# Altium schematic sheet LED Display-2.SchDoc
size A4
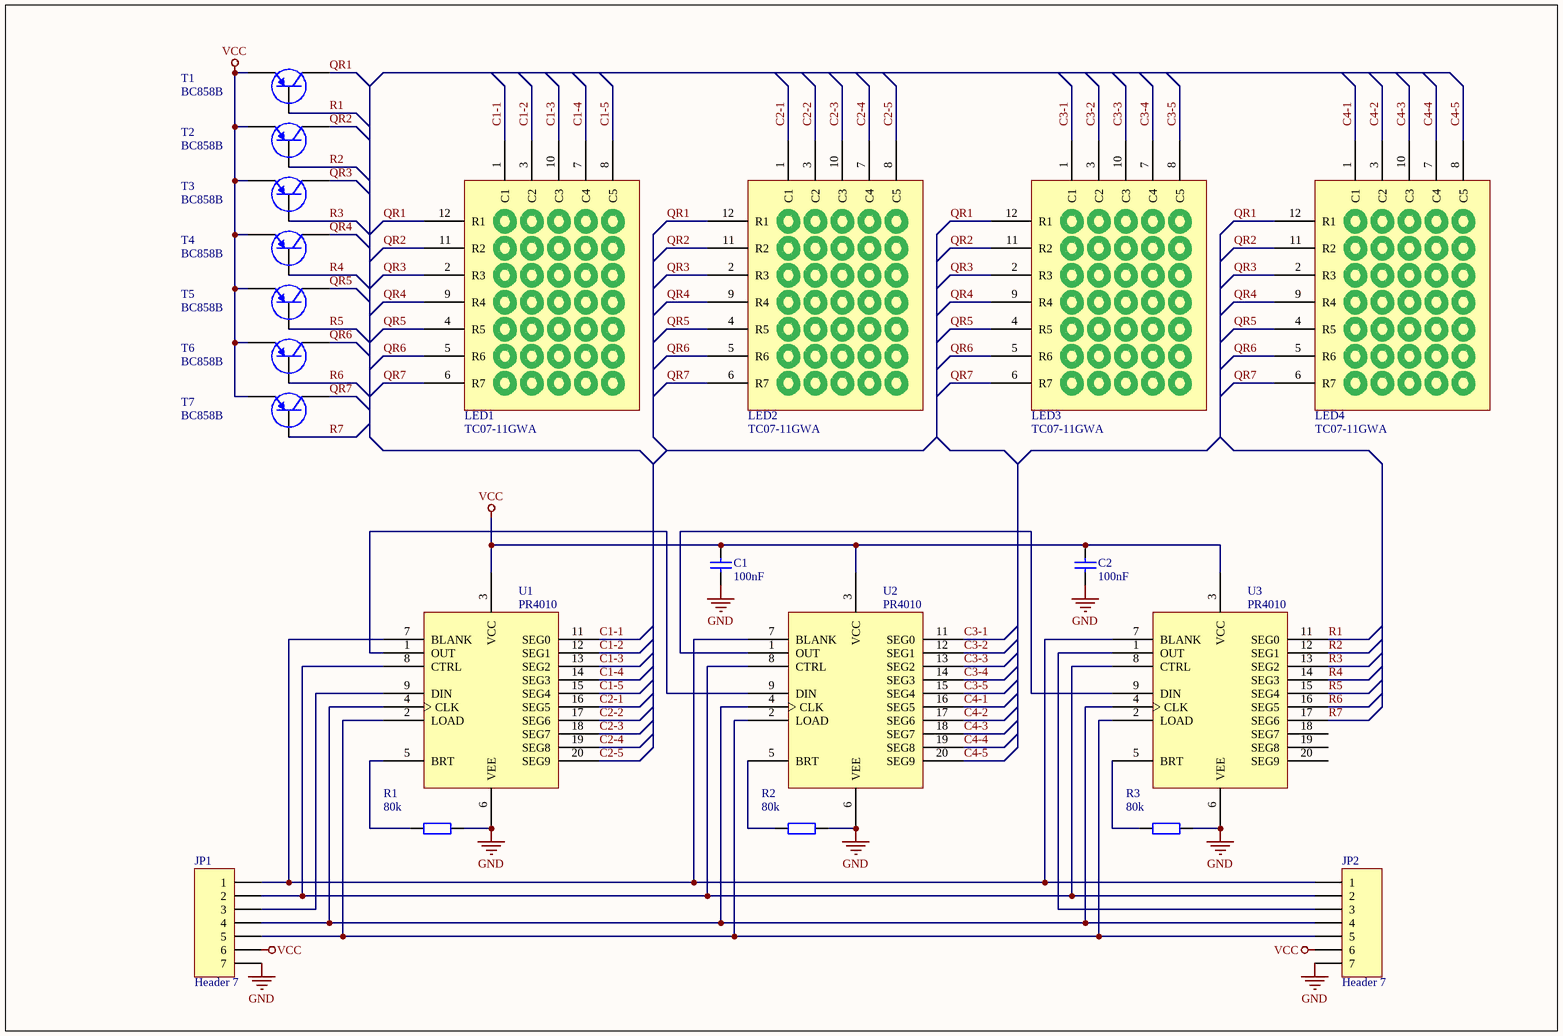
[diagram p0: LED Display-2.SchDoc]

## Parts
C1  value 100nF  [1206]  (hidden comment: Cap)
C2  value 100nF  [1206]  (hidden comment: Cap)
JP1  Header 7  [ZLACZE-K7]
JP2  Header 7  [ZLACZE-K7]
LED1  TC07-11GWA  [TC07-11]
LED2  TC07-11GWA  [TC07-11]
LED3  TC07-11GWA  [TC07-11]
LED4  TC07-11GWA  [TC07-11]
R1  value 80k  [1206]  (hidden comment: Res2)
R2  value 80k  [1206]  (hidden comment: Res2)
R3  value 80k  [1206]  (hidden comment: Res2)
T1  BC858B  [SOT-23]
T2  BC858B  [SOT-23]
T3  BC858B  [SOT-23]
T4  BC858B  [SOT-23]
T5  BC858B  [SOT-23]
T6  BC858B  [SOT-23]
T7  BC858B  [SOT-23]
U1  PR4010  [SSOP20]
U2  PR4010  [SSOP20]
U3  PR4010  [SSOP20]

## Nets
GND: C1.2 C2.2 JP1.7 JP2.7 R1.2 R2.2 R3.2 U1.6(VEE) U2.6(VEE) U3.6(VEE)
VCC: C1.1 C2.1 JP1.6 JP2.6 T1.2(E) T2.2(E) T3.2(E) T4.2(E) T5.2(E) T6.2(E) T7.2(E) U1.3(VCC) U2.3(VCC) U3.3(VCC)
C1-1: LED1.1(C1) U1.11(SEG0)
C1-2: LED1.3(C2) U1.12(SEG1)
C1-3: LED1.10(C3) U1.13(SEG2)
C1-4: LED1.7(C4) U1.14(SEG3)
C1-5: LED1.8(C5) U1.15(SEG4)
C2-1: LED2.1(C1) U1.16(SEG5)
C2-2: LED2.3(C2) U1.17(SEG6)
C2-3: LED2.10(C3) U1.18(SEG7)
C2-4: LED2.7(C4) U1.19(SEG8)
C2-5: LED2.8(C5) U1.20(SEG9)
C3-1: LED3.1(C1) U2.11(SEG0)
C3-2: LED3.3(C2) U2.12(SEG1)
C3-3: LED3.10(C3) U2.13(SEG2)
C3-4: LED3.7(C4) U2.14(SEG3)
C3-5: LED3.8(C5) U2.15(SEG4)
C4-1: LED4.1(C1) U2.16(SEG5)
C4-2: LED4.3(C2) U2.17(SEG6)
C4-3: LED4.10(C3) U2.18(SEG7)
C4-4: LED4.7(C4) U2.19(SEG8)
C4-5: LED4.8(C5) U2.20(SEG9)
QR1: LED1.12(R1) LED2.12(R1) LED3.12(R1) LED4.12(R1) T1.3(C)
QR2: LED1.11(R2) LED2.11(R2) LED3.11(R2) LED4.11(R2) T2.3(C)
QR3: LED1.2(R3) LED2.2(R3) LED3.2(R3) LED4.2(R3) T3.3(C)
QR4: LED1.9(R4) LED2.9(R4) LED3.9(R4) LED4.9(R4) T4.3(C)
QR5: LED1.4(R5) LED2.4(R5) LED3.4(R5) LED4.4(R5) T5.3(C)
QR6: LED1.5(R6) LED2.5(R6) LED3.5(R6) LED4.5(R6) T6.3(C)
QR7: LED1.6(R7) LED2.6(R7) LED3.6(R7) LED4.6(R7) T7.3(C)
R1: T1.1(B) U3.11(SEG0)
R2: T2.1(B) U3.12(SEG1)
R3: T3.1(B) U3.13(SEG2)
R4: T4.1(B) U3.14(SEG3)
R5: T5.1(B) U3.15(SEG4)
R6: T6.1(B) U3.16(SEG5)
R7: T7.1(B) U3.17(SEG6)
NetJP1_1: JP1.1 JP2.1 U1.7(BLANK) U2.7(BLANK) U3.7(BLANK)
NetJP1_2: JP1.2 JP2.2 U1.8(CTRL) U2.8(CTRL) U3.8(CTRL)
NetJP1_3: JP1.3 U1.9(DIN)
NetJP1_4: JP1.4 JP2.4 U1.4(CLK) U2.4(CLK) U3.4(CLK)
NetJP1_5: JP1.5 JP2.5 U1.2(LOAD) U2.2(LOAD) U3.2(LOAD)
NetJP2_3: JP2.3 U3.1(OUT)
NetR1_1: R1.1 U1.5(BRT)
NetR2_1: R2.1 U2.5(BRT)
NetR3_1: R3.1 U3.5(BRT)
NetU1_1: U1.1(OUT) U2.9(DIN)
NetU2_1: U2.1(OUT) U3.9(DIN)

Not connected (* = marked no-connect by the designer): U3 18(SEG7) 19(SEG8) 20(SEG9)

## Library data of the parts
C1 C2 = Cap: Capacitor
JP1 JP2 = Header 7: Header, 7-Pin
R1-R3 = Res2: Resistor
T1-T7 = PNP: PNP Bipolar Transistor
